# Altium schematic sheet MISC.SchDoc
size A4; SheetNumber: 7; SheetTotal: 16
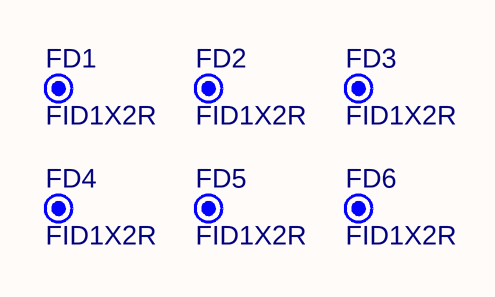
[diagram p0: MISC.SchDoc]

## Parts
FD1  FID1X2R  [FID1X2R]  (no BOM)
FD2  FID1X2R  [FID1X2R]  (no BOM)
FD3  FID1X2R  [FID1X2R]  (no BOM)
FD4  FID1X2R  [FID1X2R]  (no BOM)
FD5  FID1X2R  [FID1X2R]  (no BOM)
FD6  FID1X2R  [FID1X2R]  (no BOM)

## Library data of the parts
FD1-FD6 = CMP-00028-00005-4: Fiducial - Round 1x2mm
